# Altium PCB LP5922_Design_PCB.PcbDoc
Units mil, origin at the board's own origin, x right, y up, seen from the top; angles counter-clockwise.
Board outline 3530 x 2780 mil, 4 copper layers (Top Layer, Signal Layer 1, Signal Layer 2, Bottom Layer), stack 79.834 mil thick; 57 components, 18 nets, 103 pads, 46 vias.
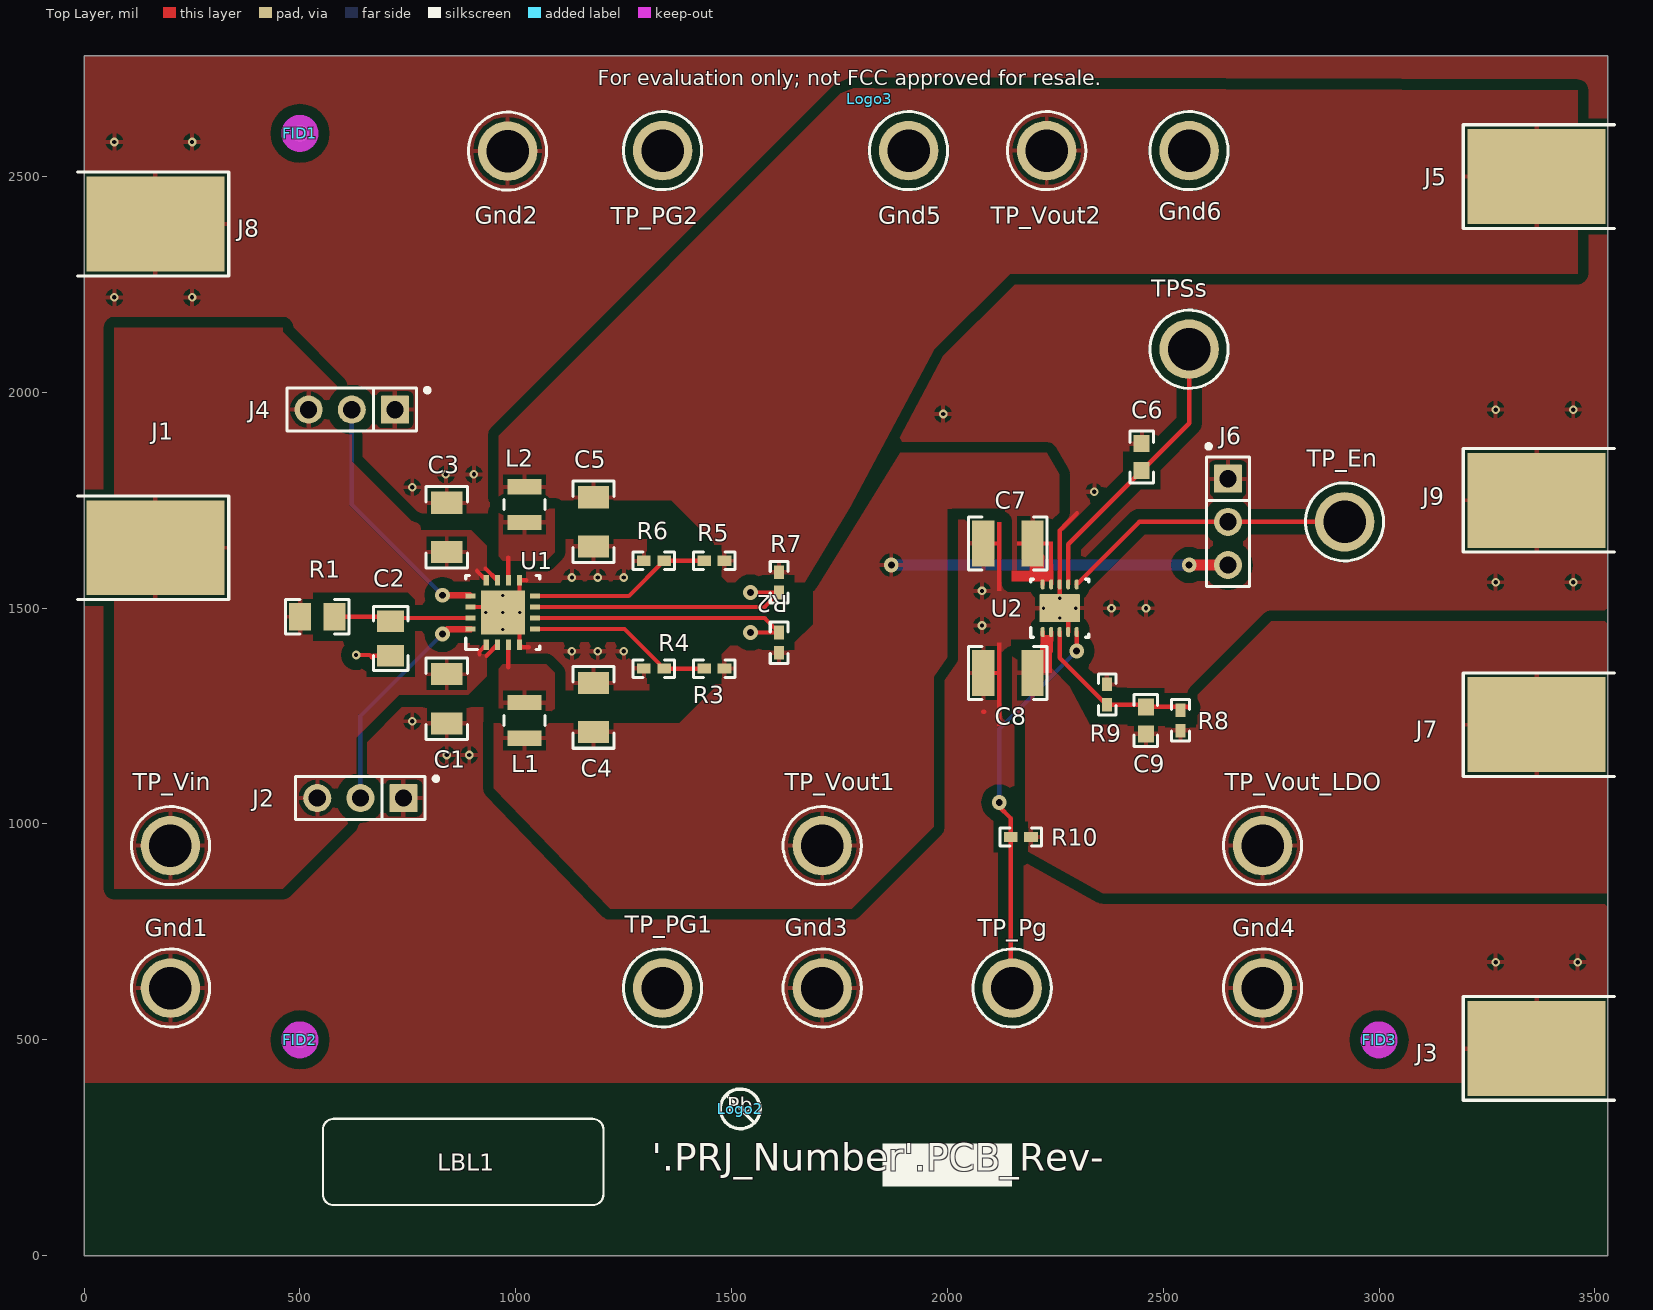
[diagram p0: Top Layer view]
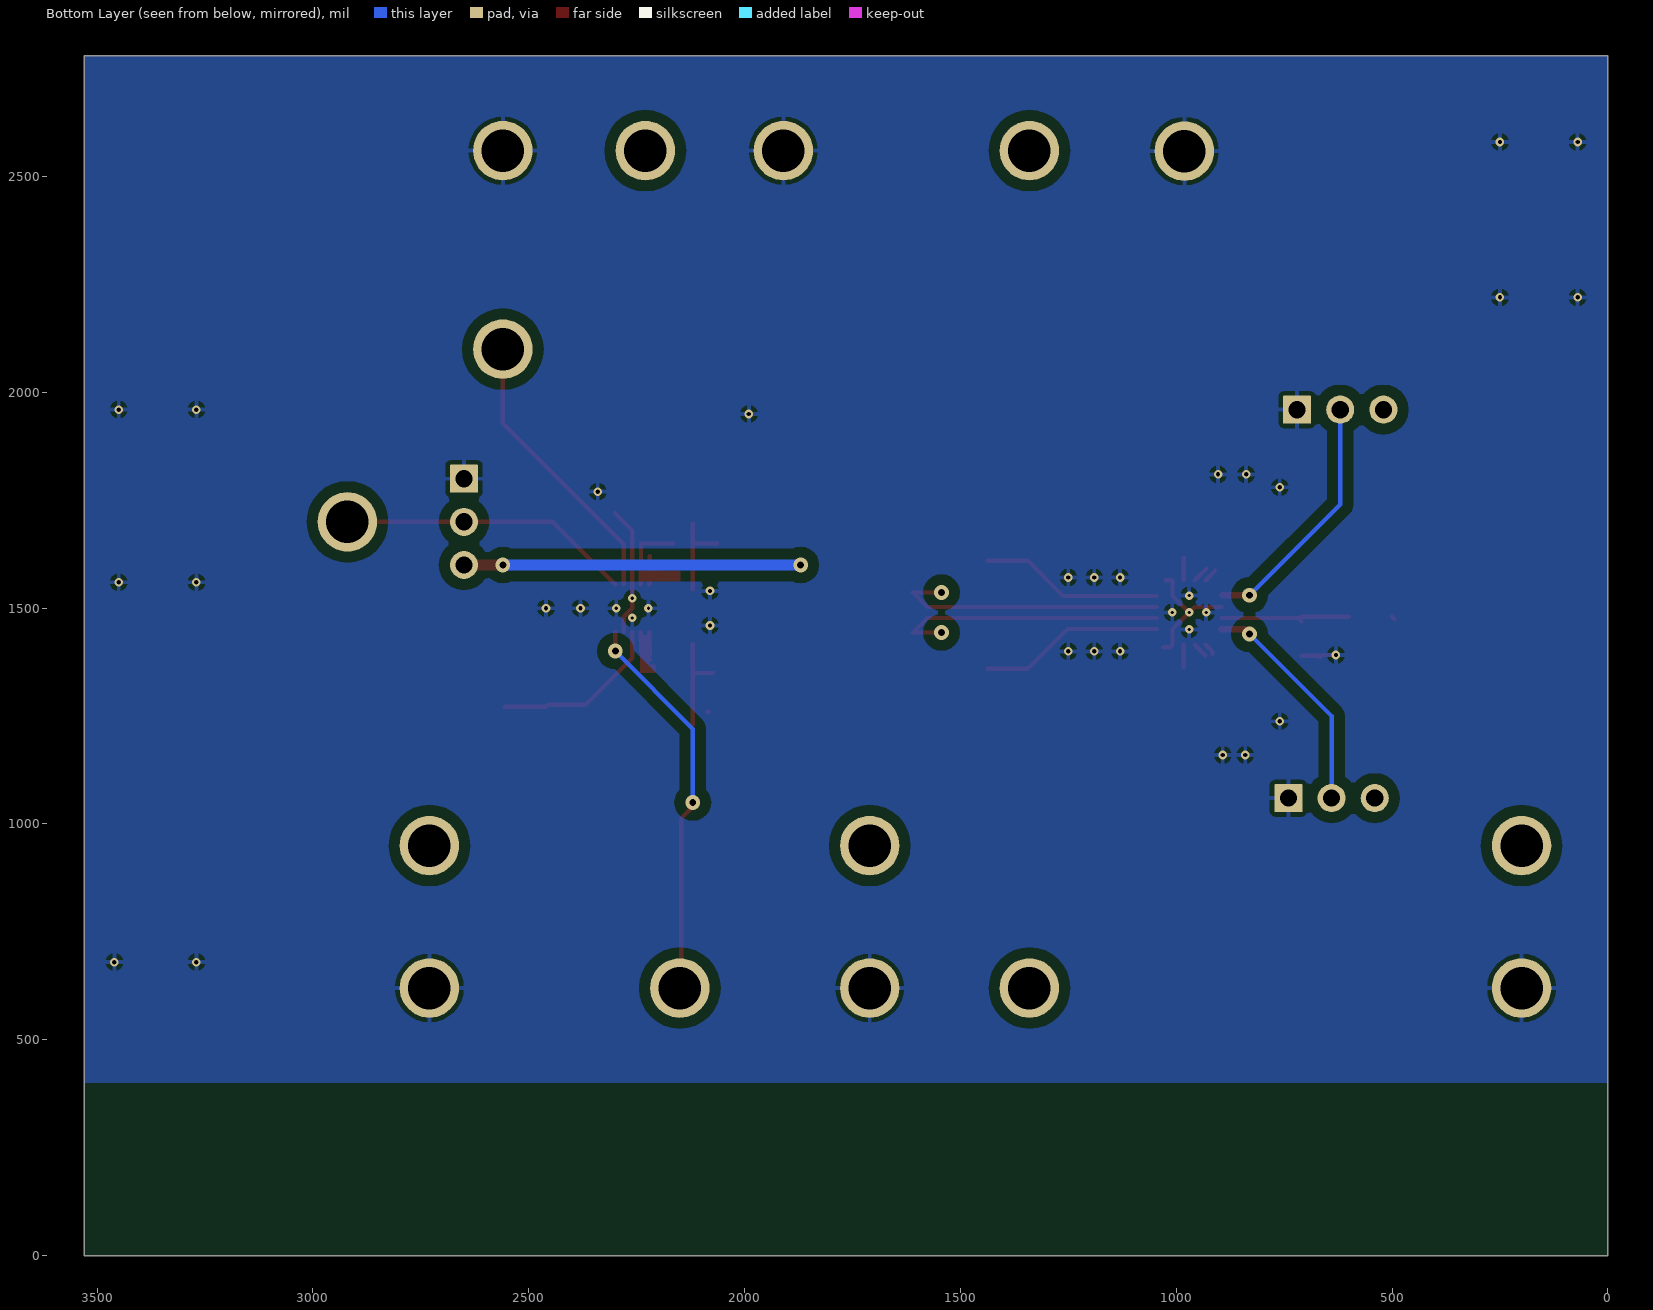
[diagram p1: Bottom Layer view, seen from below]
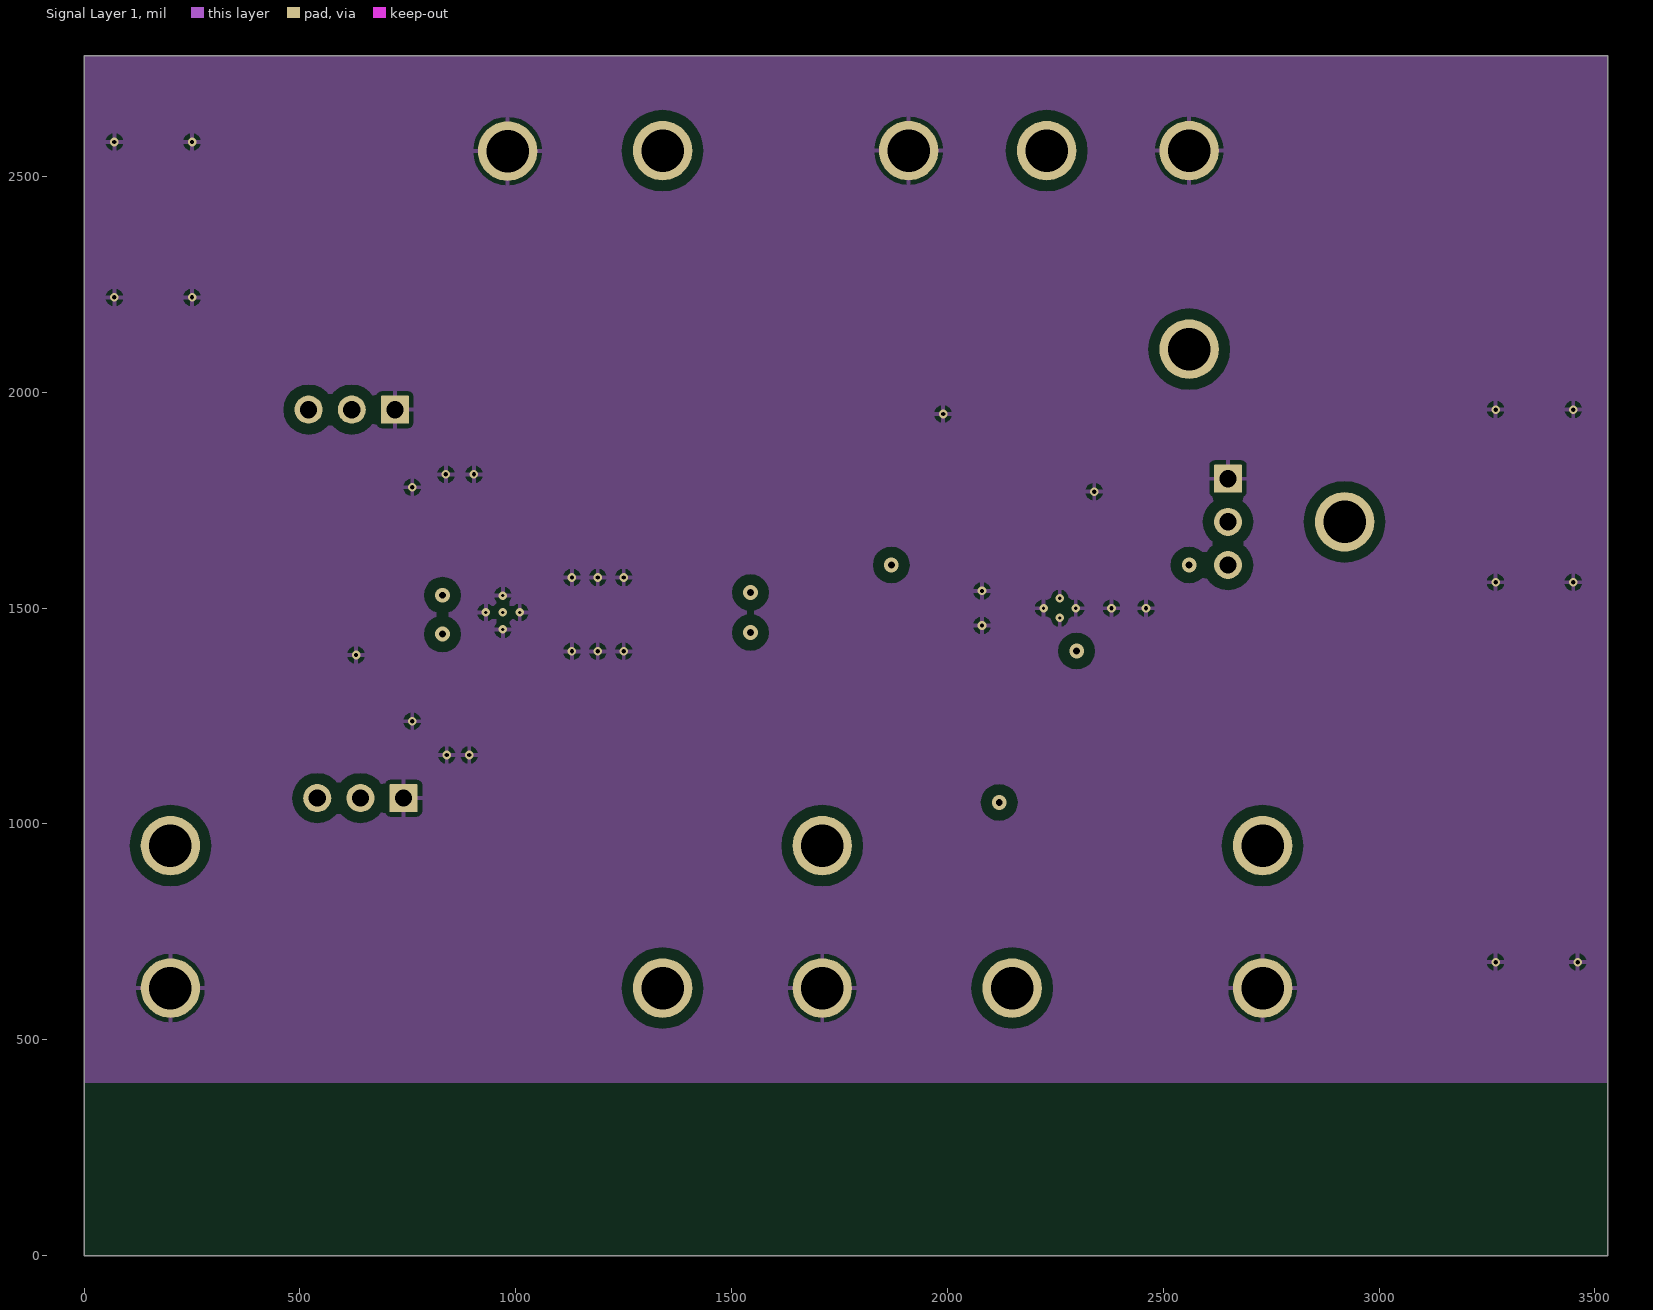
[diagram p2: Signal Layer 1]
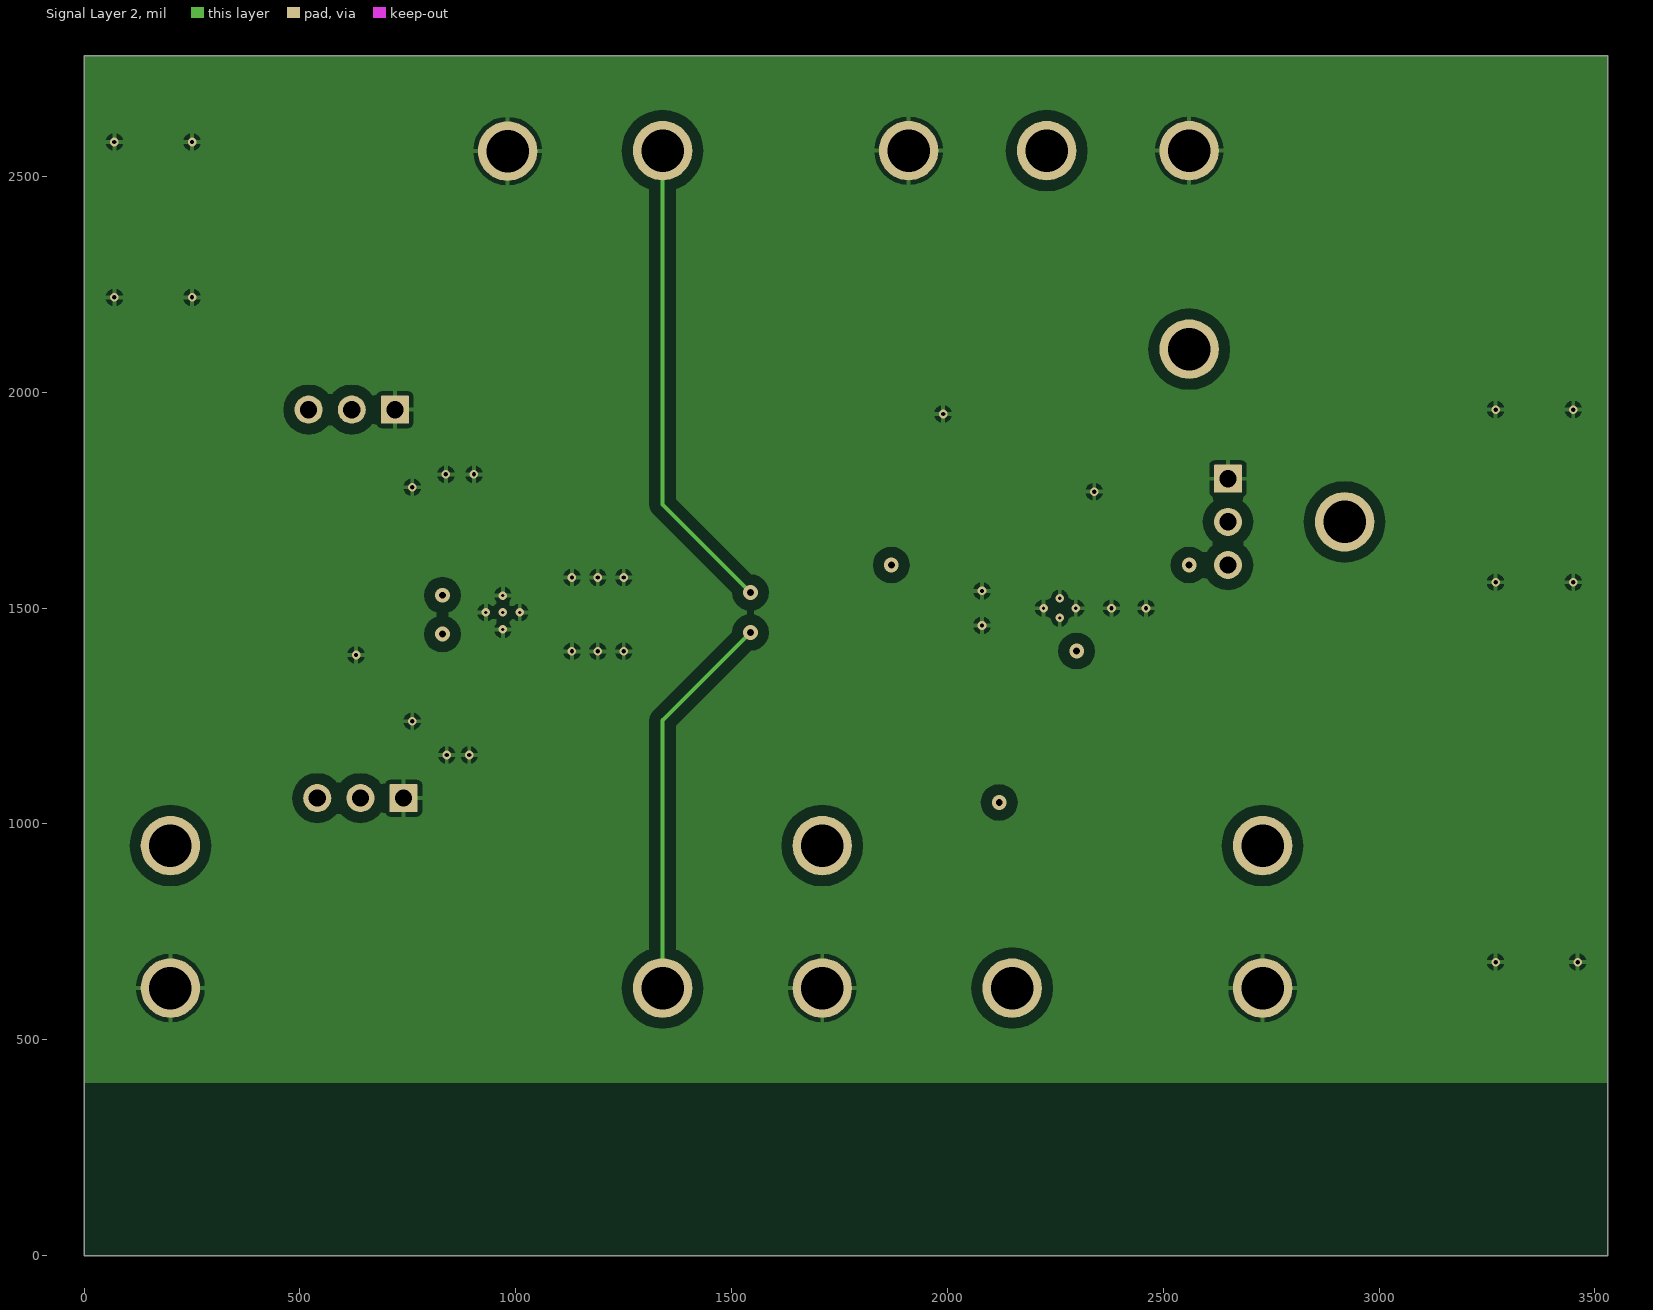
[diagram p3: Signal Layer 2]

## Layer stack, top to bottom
Top Solder: solder mask 0.4, Solder Resist, Dk 3.5
Top Layer: signal copper 1.4
Dielectric1: core 59.2, FR-4, Dk 4.8
Signal Layer 1: signal copper 1.417
Dielectric 3: prepreg 5, Dk 4.2
Signal Layer 2: signal copper 1.417
Dielectric 2: core 10, Dk 4.2
Bottom Layer: signal copper 1.4
Bottom Solder: solder mask 0.4, Solder Resist, Dk 3.5

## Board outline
0,0 3530,0 3530,2780 0,2780

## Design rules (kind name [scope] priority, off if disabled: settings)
AcuteAngle [All] p1: minimum=4.50000000000000E+0001 checktracksonly=FALSE
AssemblyTestPointUsage [All] p1: valid=2
Clearance Clearance_Keepouts [((IsTrack Or IsArc) And Not InPoly) And IsFree and IsKeepOut vs ((IsTrack Or IsArc) And Not InPoly) And IsFree and IsKeepOut] p1: gap=0
Clearance Clearance_Poly [InPolygon] p2: gap=25
Clearance [All] p3: gap=7.87
ComponentClearance ComponentClearance_MountingHoles_FiducialMarks [InComponentClass('Mounting Holes') vs InComponentClass('FiducialMark')] p1: gap=50 collisioncheckmode=3 verticalgap=10 showdistances=FALSE
ComponentClearance ComponentClearance_Shunt [InComponentClass('Header') vs InComponentClass('Shunt')] p2: gap=0 collisioncheckmode=3 verticalgap=0 showdistances=FALSE
ComponentClearance ComponentClearance_Logo [InComponentClass('Logo')] p3: gap=50 collisioncheckmode=3 verticalgap=10 showdistances=FALSE
ComponentClearance ComponentClearance_ScrewToNut [(HasFootprint('NY PMS 440 0025 PH')) vs (HasFootprint('Keystone_1902C'))] p4: gap=5 collisioncheckmode=3 verticalgap=10 showdistances=FALSE
ComponentClearance ComponentClearance_MountingHoles [InComponentClass('Mounting Holes')] p5: gap=250 collisioncheckmode=3 verticalgap=100000 showdistances=FALSE
ComponentClearance ComponentClearance_SmallPassives [HasFootprint('0201*') or HasFootprint('0402*') or HasFootprint('0508') or HasFootprint('0603*') or HasFootprint('0612') or HasFootprint('0805*') or HasFootprint('0815*') or HasFootprint('0830*') or HasFootprint('1206*') or HasFootprint('1210*') or HasFootprint('1808*') or HasFootprint('1812*') or HasFootprint('1825*') or HasFootprint('2010*') or HasFootprint('2220*') or HasFootprint('2225*') or HasFootprint('2512*') or HasFootprint('2728*') or HasFootprint('3518*') vs HasFootprint('0201*') or HasFootprint('0402*') or HasFootprint('0508') or HasFootprint('0603*') or HasFootprint('0612') or HasFootprint('0805*') or HasFootprint('0815*') or HasFootprint('0830*') or HasFootprint('1206*') or HasFootprint('1210*') or HasFootprint('1808*') or HasFootprint('1812*') or HasFootprint('1825*') or HasFootprint('2010*') or HasFootprint('2220*') or HasFootprint('2225*') or HasFootprint('2512*') or HasFootprint('2728*') or HasFootprint('3518*')] p6: gap=14.96 collisioncheckmode=3 verticalgap=10 showdistances=FALSE
ComponentClearance ComponentClearance_THtoSMT [IsThruComponent vs IsSMTComponent] p7: gap=40 collisioncheckmode=3 verticalgap=30 showdistances=FALSE
ComponentClearance ComponentClearance_THtoTH [IsThruComponent vs IsThruComponent] p8: gap=30 collisioncheckmode=3 verticalgap=30 showdistances=FALSE
ComponentClearance [All] p9: gap=30 collisioncheckmode=3 verticalgap=10 showdistances=FALSE
DiffPairsRouting [All] p1: maxlimit=100 minlimit=10 mostfreqgap=10 toplayer_minwidth=15 toplayer_maxwidth=15 toplayer_prefwidth=15 midlayer1_minwidth=15 midlayer1_maxwidth=15 midlayer1_prefwidth=15 midlayer2_minwidth=15 midlayer2_maxwidth=15 midlayer2_prefwidth=15 bottomlayer_minwidth=15 bottomlayer_maxwidth=15 bottomlayer_prefwidth=15 maxuncoupledlength=1000
FabricationTestPointUsage TestPointUsage [All] p1: valid=2 allowmultiple=FALSE
FabricationTestpoint Testpoint [All] p1: side=3 testpointundercomponent=TRUE minsize=40 maxsize=100 preferedsize=60 minholesize=0 maxholesize=40 preferedholesize=32 testpointgrid=1 allowsidetop=TRUE allowsidebottom=TRUE usegrid=TRUE gridtolerance=0.01
FanoutControl Fanout_LCC [IsLCC] p1: bgadir=Out bgaviamode=Centered fanoutstyle=Auto fanoutdirection=Alternating viagrid=1 // Fanout_LCC (Default Rule)
FanoutControl Fanout_BGA [IsBGA] p2: bgadir=Out bgaviamode=Centered fanoutstyle=Auto fanoutdirection=Alternating viagrid=1 // Fanout_BGA (Default Rule)
FanoutControl Fanout_Default [All] p4: bgadir=Out bgaviamode=Centered fanoutstyle=Auto fanoutdirection=Alternating viagrid=1 // Fanout_Default (Default Rule)
FanoutControl Fanout_Small [(CompPinCount < 5)] p5: bgadir=Out bgaviamode=Centered fanoutstyle=Auto fanoutdirection=OutThenIn viagrid=1 // Fanout_Small (Default Rule)
HoleSize [All] p1: absolutevalues=TRUE maxlimit=251 minlimit=7.87 maxpercent=80.000 minpercent=20.000
MinimumAnnularRing MinimumAnnularRing_ThermalPadVias [IsVia and InAnyComponent] p1: minimumring=5.91
MinimumAnnularRing [All] p2: minimumring=8
MinimumSolderMaskSliver MinimumSolderMaskSliver_Logo [InComponentClass('Logo') vs InComponentClass('Logo')] p1: minsoldermaskwidth=0.7
MinimumSolderMaskSliver [All] p2: minsoldermaskwidth=3.94
PlaneConnect [All] p1: planeconnectstyle=Relief reliefexpansion=10 reliefentries=4 reliefconductorwidth=10 reliefairgap=10
PolygonConnect [All] p1: connectstyle=Relief reliefconductorwidth=10 reliefentries=4 polygonreliefangle="90 Angle" airgapwidth=10
RoutingVias ThermalPadVias [IsVia and InAnyComponent] p1: holewidth=7.87 width=19.68 viastyle="Through Hole" minholewidth=7.87 minwidth=19.68 maxholewidth=12.99 maxwidth=23.62
RoutingVias [All] p2: holewidth=16 width=34 viastyle="Through Hole" minholewidth=7.87 minwidth=26 maxholewidth=40 maxwidth=65
SilkToBoardRegionClearance [Not ((IsComment or IsDesignator) And (Hide <> 'False')) and not InRegion(1000,500,4000,800)] p1:
SilkToSilkClearance SilkToSilkClearance_Pb-FreeLogo [(HasFootprint('Pb-Free_Overlay_Medium') OR HasFootprint('Pb-Free_Overlay_Small')) vs (HasFootprint('Pb-Free_Overlay_Medium') OR HasFootprint('Pb-Free_Overlay_Small'))] p1: silktosilkclearance=0
SilkToSilkClearance [All] p2: silktosilkclearance=4
SilkToSolderMaskClearance SilkToComponentPadClearance [IsPad and InAnycomponent] p1: minsilkscreentomaskgap=5 clearancetoexposedcopper=TRUE
SilkToSolderMaskClearance "Silk to Solder Mask Opening" [All] p2: minsilkscreentomaskgap=4 clearancetoexposedcopper=FALSE
SolderMaskExpansion [All] p1: expansion=1.97
Width [All] p1: maxlimit=100 minlimit=6 preferedwidth=10 checkconnectedcopper=TRUE
15 further rules are at their usual default settings.

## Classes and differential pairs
component class Label: LBL1
component class AssemblyNote: ZZ1 ZZ2 ZZ3 ZZ4
component class FiducialMark: FID1 FID2 FID3
component class LP5922_Design_EVM_Hardware: FID1 FID2 FID3 LBL1 Logo2 Logo3 ZZ1 ZZ2 ZZ3 ZZ4
component class Header: J2 J4 J6
component class LP5922_Design_BlankSheet: C1 C2 C3 C4 C5 C6 C7 C8 C9 Gnd1 Gnd2 Gnd3 Gnd4 Gnd5 Gnd6 J1 J2 J3 J4 J5 J6 J7 J8 J9 L1 L2 R1 R2 R3 R4 R5 R6 R7 R8 R9 R10 TP_En TP_Pg TP_PG1 TP_PG2 TP_Vin TP_Vout1 TP_Vout2 TP_Vout_LDO TPSs TPVout2 U1 U2

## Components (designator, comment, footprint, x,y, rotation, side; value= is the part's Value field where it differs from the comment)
C1 "C3216X5R0J226M" 1206 840,1290 r270 top
C2 "0805YC474JAT2A" 0805_HV 710,1430 r270 top
C3 "C3216X5R0J226M" 1206 840,1687.09 r90 top
C4 "C3216X5R0J476M" 1206 1180,1270 r90 top
C5 "C3216X5R0J476M" 1206 1180,1700 r270 top
C6 "GRM188R71A124KA01D" 0603 2450,1850 r90 top
C7 "C1210C226K9RACTU" 1210 2140,1650 r180 top
C8 "C1210C226K9RACTU" 1210 2140,1350 r180 top
C9 "GRM188R71H103KA01D" 0603 2460,1240 r90 top
FID1 "Fiducial" Fiducial10-20 500,2600 r0 top
FID2 "Fiducial" Fiducial10-20 500,500 r0 top
FID3 "Fiducial" Fiducial10-20 3000,500 r0 top
Gnd1 "Suggest using a net name here" Keystone1502-2 200,620 r0 top
Gnd2 "Suggest using a net name here" Keystone1502-2 981,2559 r0 top
Gnd3 "Suggest using a net name here" Keystone1502-2 1710,620 r0 top
Gnd4 "Suggest using a net name here" Keystone1502-2 2730,620 r0 top
Gnd5 "Suggest using a net name here" Keystone1502-2 1910,2560 r0 top
Gnd6 "Suggest using a net name here" Keystone1502-2 2560,2560 r0 top
J1 "6091" 6091 -20,1640 r0 top
J2 "HTSW-103-07-G-S" Samtec_HTSW-103-07-G-S 640,1060 r180 top
J3 "6092" 6092 3550,480 r180 top
J4 "HTSW-103-07-G-S" Samtec_HTSW-103-07-G-S 620,1960 r180 top
J5 "6091" 6091 3550,2500 r180 top
J6 "HTSW-103-07-G-S" Samtec_HTSW-103-07-G-S 2650,1700 r270 top
J7 "6091" 6091 3550,1230 r180 top
J8 "6092" 6092 -20,2390 r0 top
J9 "6092" 6092 3550,1750 r180 top
L1 "DFE252012PD-1R0M" DFE252012P 1020,1240 r270 top
L2 "DFE252012PD-1R0M" DFE252012P 1020,1740 r90 top
LBL1 "Size: 0.65\" x 0.20 \"" Label_650x200 878,217 r0 top
Logo2 "Pb-Free Symbol" Pb-Free_Overlay_Small 1520,340 r0 top
Logo3 "FCC disclaimer" FCC_disclaimer 1820,2680 r0 top
R1 "CRCW08054R99FKEA" 0805_HV 540,1480 r0 top
R2 "CRCW040210K0DHEDP" 0402 1610,1420 r270 top
R3 "CRCW0402619RFKED" 0402 1460,1360 r0 top
R4 "CRCW040210K0DHEDP" 0402 1320,1360 r0 top
R5 "CRCW040216K2FKED" 0402 1460,1610 r0 top
R6 "CRCW040210K0DHEDP" 0402 1320,1610 r0 top
R7 "CRCW040210K0DHEDP" 0402 1610,1560 r90 top
R8 "CRCW040232K4FKED" 0402 2540,1240 r270 top
R9 "CRCW040212K4FKED" 0402 2370,1300 r270 top
R10 "CRCW040210K0DHEDP" 0402 2170,970 r0 top
TP_En "Suggest using a net name here" Keystone1502-2 2920,1700 r0 top
TP_Pg "Suggest using a net name here" Keystone1502-2 2150,620 r0 top
TP_PG1 "Suggest using a net name here" Keystone1502-2 1340,620 r0 top
TP_PG2 "Suggest using a net name here" Keystone1502-2 1340,2560 r0 top
TP_Vin "Suggest using a net name here" Keystone1502-2 200,950 r90 top
TP_Vout1 "Suggest using a net name here" Keystone1502-2 1710,950 r0 top
TP_Vout2 "Suggest using a net name here" Keystone1502-2 2230,2560 r90 top
TP_Vout_LDO "Suggest using a net name here" Keystone1502-2 2730,950 r90 top
TPSs "Suggest using a net name here" Keystone1502-2 2560,2100 r0 top
U1 "LM26420XSQX/NOPB" RUM0016A 970,1490 r90 top
U2 "LP592201DSCR" DSC0010J 2260,1500 r90 top
ZZ1 "This Assembly Note is for PCB labels only" AssemblyNoteLabel 185,3938 r0 top
ZZ2 "These assemblies are ESD sensitive, ESD precautions shall be observed." AssemblyNote 185,3829.11 r0 top
ZZ3 "These assemblies must be clean and free from flux and all contaminants. Use of no clean flux is not acceptable." AssemblyNote 185,3740.56 r0 top
ZZ4 "These assemblies must comply with workmanship standards IPC-A-610 Class 2, unless otherwise specified." AssemblyNote 185,3652 r0 top

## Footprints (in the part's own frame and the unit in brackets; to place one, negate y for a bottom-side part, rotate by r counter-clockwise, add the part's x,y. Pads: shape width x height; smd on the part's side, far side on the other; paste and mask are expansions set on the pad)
0402 [mm] "0402 from SM-752 data"
  rect 0.8x0.6 smd: 1(-0.6,0) 2(0.6,0)
  silkscreen extent -1.22,-0.52 1.22,0.52, body extent -0.55,-0.3 0.55,0.3, height 0.6
0603 [mm] "0603 from SM-752 data"
  rect 1x0.95 smd: 1(-0.8,0) 2(0.8,0)
  silkscreen extent -1.52,-0.69 1.52,0.69, body extent -0.87,-0.47 0.87,0.47, height 1
0805_HV [mil] "0805 with 30mil clearance between pads"
  rect 50x63 smd: 1(-40,0) 2(40,0)
  silkscreen extent -74,-40 74,40, body extent -43,-29 43,29, height 57
1206 [mm] "1206 from SM-752 data"
  rect 1.3x1.85 smd: 1(-1.45,0) 2(1.45,0)
  silkscreen extent -2.4,-1.21 2.4,1.21, body extent -1.7,-0.9 1.7,0.9, height 1.35
1210 [mm] "1210 from SM-752 data"
  rect 1.3x2.7 smd: 1(-1.45,0) 2(1.45,0)
  silkscreen extent -2.32,-1.57 2.32,1.57, body extent -1.7,-1.35 1.7,1.35, height 1.35
6091 [mil] "Keystone Insulated End Launch Banana Jack"
  rect 320x220 smd: 1(185,0)
  silkscreen extent 5,-120 355,120, body extent -666,-216 271,216, height 227
6092 [mil] "Keystone Insulated End Launch Banana Jack"
  rect 320x220 smd: 1(185,0)
  silkscreen extent 5,-120 355,120, body extent -666,-216 271,216, height 227
AssemblyNote [mil] "Assembly Note"
AssemblyNoteLabel [mil] "Assembly Note for PCB Labels"
DFE252012P [mm] "TOKO, Pad sizes increased as per request"
  rect 0.9x2 smd: 1(-1.05,0) 2(1.05,0)
  silkscreen extent -0.3,-1.2 0.3,1.2, body extent -1.35,-1.1 1.35,1.1, height 1.2
DSC0010J [mm] "SON, 10-Leads, Body 3x3mm, Pitch 0.5mm, Thermal Pad 2.4x1.65mm, TI Recommended"
  rrect100% 0.6x0.24 smd: 1(-1.4,1) 2(-1.4,0.5) 3(-1.4,0) 4(-1.4,-0.5) 5(-1.4,-1) 6(1.4,-1) 7(1.4,-0.5) 8(1.4,0) 9(1.4,0.5) 10(1.4,1)
  rrect6% 1.65x2.4 smd paste-0.825: 11(0,0)
  silkscreen extent -1.7,-1.7 1.7,1.7, body extent -1.57,-1.57 1.57,1.57, height 0.81
FCC_disclaimer [mil]
Fiducial10-20 [mm]
  round 1 smd mask+0.5: 1(0,0)
  Top Layer keep-out circle w1.178: c0,0 r0.5
Keystone1502-2 [mm] "Double Turret"
  round 3.5 hole 2.5: 1(0,0)
  silkscreen extent -2.3,-2.3 2.3,2.3, body extent -1.6,-1.6 1.59,1.6, height 5.62
Label_650x200 [mil] "Thermal Transfer Label"
  silkscreen extent -325,-100 325,100, body extent -325,-100 325,100, height 1
Pb-Free_Overlay_Small [mil]
  silkscreen extent -46,-46 46,46
RUM0016A [mm] "QFN, 16-Leads, Body 4.1x4.1mm, Pitch 0.65mm, Thermal Pad 2.6x2.6mm"
  rect 0.6x0.3 smd: 1(-1.9,0.975) 2(-1.9,0.325) 3(-1.9,-0.325) 4(-1.9,-0.975) 9(1.9,-0.975) 10(1.9,-0.325) 11(1.9,0.325) 12(1.9,0.975)
  rect 0.3x0.6 smd: 5(-0.975,-1.9) 6(-0.325,-1.9) 7(0.325,-1.9) 8(0.975,-1.9) 13(0.975,1.9) 14(0.325,1.9) 15(-0.325,1.9) 16(-0.975,1.9)
  rect 2.6x2.6 smd paste-1.3: 17(0,0)
  silkscreen extent -2.17,-2.17 2.17,2.17, body extent -2.07,-2.07 2.07,2.07, height 0.8
Samtec_HTSW-103-07-G-S [mm] "Samtec 100mil, 1x3, 230 mil above insulator"
  rrect6% 1.65x1.65 hole 1.016: 1(-2.54,0)
  round 1.65 hole 1.016: 2(0,0) 3(2.54,0)
  silkscreen extent -4.57,-1.27 3.81,1.27, body extent -3.81,-1.27 3.81,1.27, height 8.38

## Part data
C1 C3: "CAP, CERM, 22 µF, 6.3 V, +/- 20%, X5R, 1206"
C2: "CAP, CERM, 0.47 µF, 16 V, +/- 5%, X7R, 0805"
C4 C5: "CAP, CERM, 47 µF, 6.3 V, +/- 20%, X5R, 1206"
C6: "CAP, CERM, 0.12 µF, 10 V, +/- 10%, X7R, 0603"
C7 C8: "CAP, CERM, 22 µF, 6.3 V, +/- 10%, X7R, 1210"
C9: "CAP, CERM, 0.01 µF, 50 V, +/- 10%, X7R, 0603"
FID1 FID2 FID3: "Fiducial mark.  There is nothing to buy or mount."
Gnd1 Gnd2 Gnd3 Gnd4 Gnd5 Gnd6 TP_En TP_Pg TP_PG1 TP_PG2 TP_Vin TP_Vout1 TP_Vout2 TP_Vout_LDO TPSs: library part 1502-2, "Terminal, Turret, TH, Double"
J1 J5 J7: "Standard Banana Jack, Insulated, Red"
J2 J4 J6: "Header, 100mil, 3x1, Gold, TH"
J3 J8 J9: "Standard Banana Jack, Insulated, Black"
L1 L2: "Inductor, Shielded, 1 µH, 3.8 A, 0.035 ohm, AEC-Q200 Grade 1, SMD"
LBL1: library part THT-14-423-10, "Thermal Transfer Printable Labels, 0.650\" W x 0.200\" H - 10,000 per roll"
Logo2: library part Pb-Free
Logo3: library part FCC_disclaimer, "FCC_disclaimer"
R1: "RES, 4.99, 1%, 0.125 W, 0805"
R2 R4 R6 R7 R10: "RES, 10.0 k, 0.5%, 0.063 W, 0402"
R3: "RES, 619, 1%, 0.063 W, 0402"
R5: "RES, 16.2 k, 1%, 0.063 W, 0402"
R8: "RES, 32.4 k, 1%, 0.063 W, 0402"
R9: "RES, 12.4 k, 1%, 0.063 W, 0402"
U1: "Dual 2-A, High Frequency Synchronous Buck Regulator, RUM0016A (WQFN-16)"
U2: "LP592201, DSC0010J"
ZZ1: library part AssemblyNoteLabel
ZZ2 ZZ3 ZZ4: library part AssemblyNote

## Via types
v1: diameter 20, hole 10, Top Layer to Bottom Layer, 29 vias
v2: diameter 19.68, hole 7.87, Top Layer to Bottom Layer, 9 vias
v3: diameter 34, hole 16, Top Layer to Bottom Layer, 8 vias

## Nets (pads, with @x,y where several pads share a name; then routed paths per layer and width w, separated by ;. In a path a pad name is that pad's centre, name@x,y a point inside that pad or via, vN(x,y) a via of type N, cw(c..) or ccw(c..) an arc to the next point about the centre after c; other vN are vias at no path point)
GND: C1.2 C2.2 C3.2 C4.2 C5.2 C6.2 C7.2 C8.2 Gnd1.1 Gnd2.1 Gnd3.1 Gnd4.1 Gnd5.1 Gnd6.1 J2.1 J3.1 J4.1 J6.1 J8.1 J9.1 R4.1 R6.1 R9.1 U1.4 U1.9 U1.14 U1.17 U2.4 U2.8 U2.11 | length 686.6
  Top Layer w10: v1(630,1391.57) 661.57,1391.57 666.57,1386.57 670,1390 C2.2 ; U1.14 957.2,1502.8 v2(970,1490) ; 1024.09,1564.8 U1.9 1008.39,1528.39 v2(970,1490) ; 1030,1409.29 1014.29,1409.29 U1.4 1008.39,1451.61 v2(970,1490) ; 2083.07,1260 2085.04,1260 ; U2.4 2279.68,1480.32 U2.11 v2(2260,1522.64) U2.8 2260,1680 2300,1720
  other v1: 3270,680 3460,680 840,1160 892,1160 760,1238 1130,1400 1190,1400 1250,1400 2080,1460 2380,1500 2460,1500 2080,1540 3270,1560 3450,1560 1130,1571 1190,1571 1250,1571 2340,1770 760,1780 838,1810 903,1810 1990,1950 3270,1960 3450,1960 70,2220 250,2220 70,2580 250,2580
  other v2: 970,1450.63 2260,1477.36 930.63,1490 1009.37,1490 2222.6,1500 2297.4,1500 970,1529.37
NetC1_1: C1.1 C3.1 J1.1 J2.3 J4.3 R1.1 TP_Vin.1 U1.1 U1.2 U1.11 U1.12 | length 140.1
  Top Layer w10: R1.1@495,1475 R1.1 ; 910,1586.42 U1.12 ; 915.71,1393.39 915.71,1399.29 U1.1 ; 930,1592.01 U1.11 ; 932.01,1390 U1.2
NetC2_1: C2.1 R1.2 U1.15 | length 298.2
  Top Layer w10: R1.2@600,1480 C2.1@710,1480 ; C2.1 717.2,1477.2 U1.15
NetC4_1: C4.1 C7.1 J6.3 L1.2 R2.2 R3.2 TP_Vout1.1 U2.9 U2.10 | length 939.8
  Top Layer w10: C7.1@2220,1620 U2.10 ; 2240,1650 U2.9
  Top Layer w25: v3(2560,1600) J6.3
  Bottom Layer w25: v3(1870,1600) v3(2560,1600)
NetC5_1: C5.1 J5.1 L2.2 R5.2 R7.2 TP_Vout2.1
NetC6_1: C6.1 TPSs.1 U2.7 | length 661
  Top Layer w10: U2.7 2279.68,1648.19 C6.1 2560,1928.5 TPSs.1
NetC8_1: C8.1 C9.1 J7.1 R8.2 R10.2 TP_Vout_LDO.1 U2.1 U2.2 | length 128.5
  Top Layer w10: C8.1@2219.74,1380 2240.06,1400.31 ; C8.1@2220,1390 U2.1 ; 2240,1400 U2.2
NetC9_2: C9.2 R8.1 R9.2 U2.3 | length 404
  Top Layer w10: U2.3 2260,1384.88 2368.5,1276.38 R9.2 2455.12,1276.38 C9.2 2554.88,1271.5 2556.38,1270
NetJ2_2: J2.2 U1.16 | length 538.7
  Top Layer w10: v3(830,1440) v3@841.61,1451.61
  Top Layer w15: v3@841.61,1451.61 U1.16
  Bottom Layer w10: J2.2 640,1250 v3(830,1440) v3@830,1450
NetJ4_2: J4.2 U1.13 | length 582.9
  Top Layer w10: U1.13@893.58,1530 U1.13
  Top Layer w15: v3(830,1530) U1.13@893.58,1530
  Bottom Layer w10: J4.2 620,1740 v3(830,1530)
NetJ6_2: J6.2 TP_En.1 U2.6 | length 680.6
  Top Layer w10: U2.6 2444.25,1700 J6.2 TP_En.1
NetL1_1: L1.1 U1.3 | length 52.4
  Top Layer w10: 982.8,1362.8 U1.3
NetL2_1: L2.1 U1.10 | length 52.4
  Top Layer w10: U1.10 982.8,1617.2
NetR2_1: R2.1 TP_PG1.1 U1.6 | length 1553.5
  Top Layer w10: U1.6 1576.42,1477.2 R2.1 v3(1543.62,1443.62)
  Signal Layer 2 w10: TP_PG1.1 1340,1240 v3(1543.62,1443.62)
NetR3_1: R3.1 R4.2 U1.5 | length 429.5
  Top Layer w10: U1.5 1252.01,1451.61 R4.2 R3.1
NetR5_1: R5.1 R6.2 U1.8 | length 425.4
  Top Layer w10: U1.8 1262.01,1528.39 R6.2 R5.1
NetR7_1: R7.1 TP_PG2.1 U1.7 | length 1753.5
  Top Layer w10: U1.7 1576.42,1502.8 R7.1 v3(1543.62,1536.38)
  Signal Layer 2 w10: TP_PG2.1 1340,1740 v3(1543.62,1536.38)
NetR10_1: R10.1 TP_Pg.1 U2.5 | length 911.2
  Top Layer w10: v3(2120,1050) 2120,1040 2146.38,1013.62 R10.1 2146.38,623.62 TP_Pg.1 ; v3(2299.37,1400.63) U2.5
  Bottom Layer w10: v3(2120,1050) 2120,1220 v3(2299.37,1400.63)
pads on no net: FID1.1 FID2.1 FID3.1

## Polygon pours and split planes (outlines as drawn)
GND on Top Layer "TOP_LAYER_GND_P064" (solid, remove dead copper, pour order 64): 0,2780 3530,2780 3530,400 0,400 0,2780
NetC4_1 on Top Layer "TOP_LAYER_NETC4_1_P062" (solid, remove dead copper, pour order 62): 948.75,1233.14 948.75,1083.14 1218.75,803.14 1778.75,803.14 1968.75,993.14 1968.75,1341.29 2000.11,1386.07 2000.11,1416.07 2000.11,1435.45 2000.11,1456.07 1999.89,1480 1999.89,1503.93 1999.89,1523.93 1999.89,1563.93 1999.89,1579.91 1999.89,1590 1999.89,1618.71 1999.9,1640 2000.01,1679.13 2000.01,1690 2000.01,1720 2000.01,1729.99 2010,1729.99 2020.42,1729.99 2100,1729.99 2101.92,1729.91 2120.23,1729.99 2140.28,1709.95 2149.12,1701.1 2148.87,1569.88 2154.6,1564.1 2258.75,1564.1 2258.75,1573.14 2258.75,1593.14 2258.75,1633.14 2258.75,1733.14 2258.75,1810.74 2230,1860 1970,1860 1890.41,1860 1701.66,1554.72 1691.42,1539.75 1688.75,1539.75 1688.75,1463.14 1638.75,1413.14 1497.1,1413.14 1458.75,1374.79 1461.94,1371.6 1461.94,1316.33 1419.58,1273.97 1378.75,1233.14
NetC5_1 on Top Layer "TOP_LAYER_NETC5_1_P060" (solid, remove dead copper, pour order 60): 960,1900 960,1750 1360,1750 1460,1650 1460,1590 1490,1560 1670,1560 1775.01,1735.19 1970,2100 2145,2275 3460,2275 3460,2490 3460,2700 1830,2705 1782,2705 1753,2693
NetC8_1 on Top Layer "TOP_LAYER_NETC8_1_P050" (solid, remove dead copper, pour order 50): 2240,1400 2300,1400 2190,1400 2160,1400 2150,1400 2150,1285.52 2150,1257.64 2180,1252.48 2180,1120 2180,940 2360,840 3513.6,840 3530,840 3530,848.87 3530,900 3530,960 3530,1010 3530,1195.36 3530,1469.62 3454.64,1469.62 3027.97,1469.62 2930,1469.62 2749.62,1469.62 2580,1300 2580,1230 2330,1230
NetC1_1 on Top Layer "TOP_LAYER_NETC1_1_P026" (solid, remove dead copper, pour order 26): 70,1680 70,2150 460,2150 460,2140 610,1990 620,1980 620,1860 620,1840 757.93,1702.07 783,1692.63 800,1690 860.75,1690 932.38,1690 932.38,1382.38 932.38,1300 850,1300 730,1300 630,1200 630,1040 630,1020 460,850 70,850
NetL1_1 on Top Layer "TOP_LAYER_NETL1_1_P028" (solid, remove dead copper, pour order 28): 960,1370 960,1268.57 1020,1268.57 1090,1260 1090,1370 1040,1370 990,1370
NetL2_1 on Top Layer "TOP_LAYER_NETL2_1_P032" (solid, remove dead copper, pour order 32): 1090,1730 1090,1610 1010,1610 980,1610 960,1610 960,1730 980,1730 990,1730 1010,1730
GND on Signal Layer 1 "SIGNAL_LAYER_1_GND_P068" (solid, remove dead copper, pour order 68): 0,2780 3530,2780 3530,400 0,400 0,2780
GND on Signal Layer 2 "SIGNAL_LAYER_2_GND_P070" (solid, remove dead copper, pour order 70): 0,2780 3530,2780 3530,400 0,400 0,2780
GND on Bottom Layer "BOTTOM_LAYER_GND_P072" (solid, remove dead copper, pour order 72): 0,2780 3530,2780 3530,400 0,400 0,2780

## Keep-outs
Keep-Out Layer:
  text ".Layer_Name" at 577,-858.49 h60

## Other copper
Top Layer:
  rectangle net NetC4_1: 2161.5,1645 2245,1655
  rectangle net GND: 2059.69,1645 2120,1655
  rectangle net GND: 2115,1540 2125,1700
  rectangle net GND: 2070,1345 2120.31,1355
  rectangle net GND: 2115,1226.85 2125,1420
  rectangle net NetC8_1: 2206.91,1350 2242.68,1370
  rectangle net NetC8_1: 2220,1359.41 2242.68,1437.99
  rectangle net NetC4_1: 2190,1580 2220.39,1600
  rectangle net NetC4_1: 2148.87,1562.01 2240,1586.85
  pour cut-out: 750,1536.5 766.5,1520 766.5,1507.46 622.54,1507.46 593.5,1536.5
  pour cut-out: 960,1620 970,1610 960,1610
  pour cut-out: 1070,1610 1090,1630 1090,1610
  pour cut-out: 894.59,1682.7 940,1637.3 940,1682.7
  pour cut-out: 960,1370 970,1370 960,1360
  pour cut-out: 1070,1370 1090,1350 1090,1370
  pour cut-out: 780,1680 830,1680 886.26,1680 910,1680 930,1680 940,1670 940,1710 940,1720 780,1720 779.44,1680.56
  pour cut-out: 1110,1720 1380,1720 1380,1660 1110,1660
  pour cut-out: 1110,1310 1310,1310 1310,1280 1110,1280
  pour cut-out: 924.51,1230.95 924.51,1273.54 937.81,1260.24 937.81,1244.25
  pour cut-out: 730,1270 939.69,1270 934.51,1275.18 932.38,1277.31 932.38,1300 740,1300
  pour cut-out: 932.38,1342.09 890.29,1300 932.38,1300
  pour cut-out: 1309.69,1309.69 1309.69,1280 1410,1290 1440,1320 1440,1330 1309.69,1330
  pour cut-out: 1310,1530 1480,1530 1480,1550 1474.83,1550 1444.83,1580 1400,1580 1400,1642.44 1402.44,1640 1420,1640 1420,1670 1390,1700 1310,1700 1302.87,1692.87 1302.87,1642.91 1377.09,1642.91 1380,1640 1380,1580 1340,1580 1310,1550
  text ".Layer_Name" at 577,-858.49 h60
Bottom Layer:
  text ".Layer_Name" at 577,-858.49 h60

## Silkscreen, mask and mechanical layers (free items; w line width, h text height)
Top Overlay:
  region: 2150,260 1850,260 1850,160 2150,160
  text "'.PRJ_Number'.PCB_Rev-" at 1315,175.77 h108.27
  text ".Layer_Name" at 577,-858.49 h60
Bottom Overlay:
  text ".Layer_Name" at 577,-858.49 h60
Top Paste:
  text ".Layer_Name" at 577,-858.49 h60
Bottom Paste:
  text ".Layer_Name" at 577,-858.49 h60
Top Solder:
  text ".Layer_Name" at 577,-858.49 h60
  text ".Layer_Name" at 577,-858.49 h60
Bottom Solder:
  text ".Layer_Name" at 577,-858.49 h60
Drill Guide:
  text ".Layer_Name" at 577,-858.49 h60
M1 Board Outline:
  the board outline again, w10
  text ".Layer_Name" at 577,-858.49 h60
M2 Board Dimensions:
  rectangle: 125,-400 500,-275
  rectangle: 0,-275 125,-150
  lines w7: 0,-275 1000,-275 ; 125,-400 125,-150 ; 250,-400 250,-150 ; 500,-400 500,-150 ; 750,-400 750,-150 ; 0,-400 0,-150 1000,-150 1000,-400 0,-400
  text ".Layer_Name" at 577,-858.49 h60
M3 3D STEP Top:
  text ".Layer_Name" at 577,-858.49 h60
M4 3D STEP Bottom:
  text ".Layer_Name" at 577,-858.49 h60
M5 Assembly Top:
  lines w10: -292,-930.17 6308,-930.17 ; -292,-726.83 6310,-726.83 ; -292,-523.5 -292,-1133.5 3713,-1133.5 6310,-1133.5 6310,-523.5 -291.5,-523.5 -291.5,-1133.5 1284,-1133.5 ; 2173,-1133.5 2173,-523.5 ; 3440,-726.83 3440,-523.5 ; 4280,-726.83 4280,-523.5 ; 4902,-1140 4902,-937.17
  text "COMPONENTS MARKED 'DNP' SHOULD NOT BE POPULATED." at 1153.5,-318.5 h60
  text "ASSEMBLY VARIANT:" at 1153,-434 h60
  text ".VariantName" at 2189,-434 h60
  text "PCB VIEWED FROM TOP SIDE" at -228.5,-655.67 h60
  text "BOARD #:" at 2248,-655.67 h60
  text ".PRJ_Number" at 2793.5,-655.67 h60
  text "REV:" at 3638,-655.67 h60
  text ".PCB_Rev" at 3929.5,-655.67 h60
  text "SVN REV:" at 4476,-655.67 h60
  text ".VersionControl_RevNumber" at 4982,-655.67 h60
  text "TID #:" at 2248,-859 h60
  text ".TID" at 2793.5,-859 h60
  text "PLOT NAME =" at -228.5,-1064.34 h60
  text ".plot_File_Name" at 577,-1064.34 h60
  text "GENERATED    :" at 2250,-1064.34 h60
  text ".Print_Date" at 3119.5,-1064.34 h60
  text ".Print_Time" at 3848.5,-1064.34 h60
  text "TEXAS INSTRUMENTS" at 5113,-1064.34 h60
M6 Assembly Bottom:
  lines w10: -292.5,-727.33 6309.5,-727.33 ; -290.5,-930.67 6309.5,-930.67 ; 1115.5,-1140.5 1115.5,-937.67 ; 1737.5,-727.33 1737.5,-524 ; 2577.5,-727.33 2577.5,-524 ; 3844.5,-1134 3844.5,-524 ; 4733.5,-1134 6309,-1134 6309,-524 -292.5,-524 -292.5,-1134 2304.5,-1134 6309.5,-1134 6309.5,-524
  text "COMPONENTS MARKED 'DNP' SHOULD NOT BE POPULATED." at 6102,-318 h60
  text ".VariantName" at 5058,-434 h60
  text "ASSEMBLY VARIANT:" at 6097,-434 h60
  text ".VersionControl_RevNumber" at 1035.5,-656.17 h60
  text "SVN REV:" at 1541.5,-656.17 h60
  text ".PCB_Rev" at 2088,-656.17 h60
  text "REV:" at 2379.5,-656.17 h60
  text ".PRJ_Number" at 3224,-656.17 h60
  text "BOARD #:" at 3769.5,-656.17 h60
  text "PCB VIEWED FROM BOTTOM SIDE" at 6246,-656.17 h60
  text ".TID" at 3224,-859.5 h60
  text "TID #:" at 3769.5,-859.5 h60
  text "TEXAS INSTRUMENTS" at 904.5,-1064.84 h60
  text ".Print_Time" at 2169,-1064.84 h60
  text ".Print_Date" at 2898,-1064.84 h60
  text "GENERATED    :" at 3767.5,-1064.84 h60
  text ".plot_File_Name" at 5440.5,-1064.84 h60
  text "PLOT NAME =" at 6246,-1064.84 h60
M9 Title Sheet:
  drawing of 57 lines, arcs and shapes, not listed
  text "1" at 739.84,8036.5 h70
  text "2" at 3235.5,8036.5 h70
  text "3" at 5724.84,8036.5 h70
  text "4" at 8231.51,8036.5 h70
  text "5" at 10730.5,8036.5 h70
  text "6" at 13235.5,8036.5 h70
  text "A" at -416.5,6893.5 h70
  text "A" at 14383.5,6893.5 h70
  text "B" at -416.5,4513.5 h70
  text "B" at 14383.5,4513.5 h70
  text "C" at -416.5,2138.5 h70
  text "C" at 14383.5,2138.5 h70
  text "PROJECT TITLE:" at 11343.5,277.5 h45
  text "TIDA-01322" at 11393.5,144.17 h70
  text "DESIGNED FOR:" at 11343.5,-23.5 h45
  text ".PRJ_Customer" at 11393.5,-163.5 h70
  text "D" at -416.5,-231.5 h70
  text "D" at 14383.5,-231.5 h70
  text "FILE NAME:" at 11343.5,-323.5 h45
  text ".PCB_File_Name_No_Path" at 11393.5,-443.5 h70
  text "Texas Instruments (TI) and/or its licensors do not warrant the accuracy or completeness of this specification" at 6374,-605.34 h45
  text "ENGINEER:" at 11343.5,-613.5 h45
  text "LAYOUT BY:" at 12848.5,-613.5 h45
  text "or any information contained therein. TI and/or its licensors do not warrant that this design will meet" at 6329.01,-718 h45
  text "Jari Niemelä" at 12899,-768.49 h70
  text "the specifications, will be suitable for your application or fit for any particular purpose, or will operate in" at 6329.01,-830.67 h45
  text ".Layer_Name" at 577,-858.49 h60
  text "ALTIUM DESIGNER VERSION:" at 12848.5,-923.5 h45
  text "an implementation. TI and/or its licensors do not warrant that the design is production worthy. You should" at 6329.01,-943.33 h45
  text "completely validate and test your design implementation to confirm the system functionality for your application." at 6374,-1056 h45
  text ".print_Scale" at 11393.5,-1056.83 h70
  text ".Application_BuildNumber" at 12899,-1056.83 h70
  text "1" at 739.84,-1263.5 h70
  text "2" at 3235.5,-1263.5 h70
  text "3" at 5724.84,-1263.5 h70
  text "4" at 8231.51,-1263.5 h70
  text "5" at 10730.5,-1263.5 h70
  text "6" at 13235.5,-1263.5 h70
M10 Fab Notes:
  drawing of 173 lines, arcs and shapes, not listed
  text "DESIGN INFORMATION" at 12378.02,6201 h60
  text "MIN. TRACK WIDTH:" at 11733.46,6021 h60
  text "MIL" at 12984.46,6021 h60
  text "8" at 12821.7,6013 h60
  text "MIN. CLEARANCE:" at 11733.46,5889 h60
  text "0.2" at 12769.7,5889 h60
  text "mm" at 12984.46,5889 h60
  text "MIN. VIA PAD SIZE:" at 11733.46,5757 h60
  text "24" at 12799.71,5757 h60
  text "MIL" at 12984.46,5757 h60
  text "0.05mm (2MIL)" at 12428.46,5615.29 h60
  text "MINIMUM ANNULAR RING" at 11404.23,5611 h60
  text "EXTERNAL" at 13136.46,5611 h60
  text "PER" at 11604.23,5493 h60
  text "IPC-D-275 CLASS 2 LEVEL C" at 11824.23,5493 h60
  text "MIL, HOLES" at 13312.46,5380.71 h60
  text "+/-" at 12920,5380 h60
  text "+/-" at 13774,5380 h60
  text "REGISTRATION TOLERANCES:" at 11404.23,5375 h60
  text "METAL" at 12604,5375 h60
  text "5" at 13180.2,5375 h60
  text "3" at 14013.2,5375 h60
  text "MIL" at 14129.46,5375 h60
  text "+/-" at 13774,5262 h60
  text "HOLE SIZE TOLERANCE (UNLESS OTHERWISE SPECIFIED):" at 11404.23,5257 h60
  text "3" at 14013.2,5257 h60
  text "MIL" at 14129.46,5257 h60
  text "MATERIAL:" at 11329.46,5047.54 h60
  text "FR-4 High Tg" at 12315.9,4907.21 h60
  text "FR-408" at 11750.46,4898.64 h60
  text "OTHER" at 13238.46,4898.64 h60
  text "X" at 12161,4895 h60
  text "62 MIL (1.6mm) +/-10%" at 12070.56,4735.92 h60
  text "THICKNESS:" at 11404.23,4731.64 h60
  text "X" at 11942.4,4731.64 h60
  text "OTHER" at 13355.46,4731.64 h60
  text "TOLERANCE:" at 11404.23,4573.64 h60
  text "X" at 12243.53,4573.64 h60
  text "ANSI IPC-6012 TYPE 3 CLASS 2" at 12430.48,4573.64 h60
  text "OTHER +/-" at 12430.46,4417.64 h60
  text "BOW & TWIST:" at 11404.23,4260.64 h60
  text "X" at 12243.53,4260.64 h60
  text "ANSI IPC-6012 TYPE 3 CLASS 2" at 12430.48,4260.64 h60
  text "OTHER +/-" at 12430.46,4102.13 h60
  text "DRILLING:" at 11329.46,3963.64 h60
  text "REFERENCE:" at 11404.23,3846.64 h60
  text "X" at 12052.46,3846.64 h60
  text "AS SHOWN" at 12239.46,3846.64 h60
  text "X" at 12953.46,3846.64 h60
  text "NC_DRILL FILES" at 13090.46,3846.64 h60
  text "PTH COPPER THICKNESS:" at 11404.23,3688.64 h60
  text "X" at 12534.46,3688.64 h60
  text "20-30 um" at 12671.46,3688.64 h60
  text "OTHER" at 13388.46,3688.64 h60
  text "BOARD FINISH:" at 11329.46,3529.64 h60
  text "SILKSCREEN:" at 11484.68,3411.64 h60
  text "X" at 12433.46,3411.64 h60
  text "TOP" at 12559.46,3411.64 h60
  text "X" at 12943.46,3411.64 h60
  text "BOTTOM" at 13070.46,3411.64 h60
  text "SILKSCREEN COLOR:" at 11484.68,3244.64 h60
  text "X" at 12432.42,3244.64 h60
  text "WHITE" at 12559.46,3244.64 h60
  text "OTHER" at 13070.46,3244.64 h60
  text "X" at 12563.42,3085.44 h60
  text "GREEN" at 12690.46,3085.44 h60
  text "OTHER" at 13308.46,3085.44 h60
  text "SOLDER RESIST COLOR:" at 11484.68,3074.64 h60
  text "X" at 12563.42,2915.44 h60
  text "MATTE" at 12690.46,2915.44 h60
  text "SEMI-GLOSS" at 13308,2914.8 h60
  text "IMMERSION GOLD (ENIG)" at 12390.46,2726.92 h60
  text "ENEPIG" at 13728,2723.64 h60
  text "SURFACE FINISH:" at 11329.46,2722.64 h60
  text "X" at 12203.51,2722.64 h60
  text "IMM. TIN/SILVER OR EQUIV" at 11659,2565.64 h60
  text "OTHER" at 13090.46,2565.64 h60
  text "ARRAY/PANEL:" at 11329.46,2386.64 h60
  text "CUT AND TRIM PER M1 BOARD OUTLINE" at 12390.46,2382.35 h60
  text "N.C. ROUTE" at 12390.46,2230.64 h60
  text "X" at 13069.46,2230.64 h60
  text "V. SCORE" at 13256.46,2230.64 h60
  text "CERTIFICATION:" at 11329.46,2093.64 h60
  text "MATERIALS AND WORKMANSHIP FOR ALL PCBS" at 12054.46,2093.64 h60
  text "TO MEET OR EXCEED THE REQUIREMENTS OF:" at 12054.46,1995.64 h60
  text "X" at 11680.96,1859.13 h60
  text "ANSI IPC-A-600F CLASS ->" at 11819.96,1859.13 h60
  text "X" at 13459.02,1859.13 h60
  text "2" at 13577.96,1859.14 h60
  text "1" at 13262.96,1857.64 h60
  text "3" at 13931.96,1857.64 h60
  text "X" at 12495.02,1699.64 h60
  text "RoHS" at 12631.96,1699.64 h60
  text "OTHER" at 13276.36,1699.64 h60
  text "PER ORDER" at 13673.42,1699.64 h60
  text "ALL BOARDS MUST MEET OR EXCEED UL94-V0 REQUIREMENTS." at 11357,1534 h60
  text "PCB MUST BEAR THE UL94V-0 UL REGISTERED MATERIAL ID NUMBER" at 11357,1414 h60
  text "ADDITIONAL REQUIREMENTS:" at 11329.46,1240.64 h60
  text "MICROSECTION:" at 11404.23,1125.64 h60
  text "YES" at 12309.96,1125.64 h60
  text "REQUIRED" at 13171.46,969.49 h60
  text "BARE BOARD ELEC. TEST:" at 11404.23,966.64 h60
  text "NONE" at 12709.96,966.64 h60
  text "X" at 13044.46,966.64 h60
  text "PER ORDER" at 13763.46,966.64 h60
  text ".Layer_Name" at 577,-858.49 h60
M11 Gerber Information:
  lines w10: -292,-930.17 6308,-930.17 ; -292,-726.83 6310,-726.83 ; -292,-523.5 -292,-1133.5 3713,-1133.5 6310,-1133.5 6310,-523.5 -291.5,-523.5 -291.5,-1133.5 1284,-1133.5 ; 2173,-1133.5 2173,-523.5 ; 3440,-726.83 3440,-523.5 ; 4280,-726.83 4280,-523.5 ; 4902,-1140 4902,-937.17
  text "ALL ARTWORK VIEWED FROM TOP SIDE" at -228.5,-655.67 h60
  text "BOARD #:" at 2248,-655.67 h60
  text ".PRJ_Number" at 2793.5,-655.67 h60
  text "REV:" at 3638,-655.67 h60
  text ".PCB_Rev" at 3929.5,-655.67 h60
  text "SVN REV:" at 4476,-655.67 h60
  text ".VersionControl_RevNumber" at 4982,-655.67 h60
  text "LAYER NAME =" at -228.5,-858.49 h60
  text "TID #:" at 2248,-859 h60
  text ".TID" at 2793.5,-859 h60
  text "PLOT NAME =" at -228.5,-1064.34 h60
  text ".plot_File_Name" at 577,-1064.34 h60
  text "GENERATED    :" at 2250,-1064.34 h60
  text ".Print_Date" at 3119.5,-1064.34 h60
  text ".Print_Time" at 3848.5,-1064.34 h60
  text "TEXAS INSTRUMENTS" at 5113,-1064.34 h60
M12 Stackup:
  drawing of 191 lines, arcs and shapes, not listed
  text "Layer" at 9790.34,7830 h60
  text "Name" at 10200.26,7830 h60
  text "Material" at 11130,7830 h60
  text "Thickness" at 11989.77,7830 h60
  text "Constant" at 12639.6,7830 h60
  text "Board Layer Stack" at 13209.46,7830 h60
  text "1" at 9790.34,7710 h60
  text "Top Overlay" at 10200.26,7710 h60
  text "2" at 9790.34,7590 h60
  text "Top Solder" at 10200.26,7590 h60
  text "Solder Resist" at 11130,7590 h60
  text "0.40mil" at 11989.77,7590 h60
  text "3.5" at 12639.6,7590 h60
  text "3" at 9790.34,7470 h60
  text "Top Layer" at 10200.26,7470 h60
  text "Copper" at 11130,7470 h60
  text "1.40mil" at 11989.77,7470 h60
  text "4" at 9790.34,7350 h60
  text "Dielectric1" at 10200.26,7350 h60
  text "FR-4" at 11130,7350 h60
  text "59.20mil" at 11989.77,7350 h60
  text "4.8" at 12639.6,7350 h60
  text "5" at 9790.34,7230 h60
  text "Bottom Layer" at 10200.26,7230 h60
  text "Copper" at 11130,7230 h60
  text "1.40mil" at 11989.77,7230 h60
  text "6" at 9790.34,7110 h60
  text "Bottom Solder" at 10200.26,7110 h60
  text "Solder Resist" at 11130,7110 h60
  text "0.40mil" at 11989.77,7110 h60
  text "3.5" at 12639.6,7110 h60
  text "7" at 9790.34,6990 h60
  text "Bottom Overlay" at 10200.26,6990 h60
  text ".Layer_Name" at 577,-858.49 h60
M13 Component Bodies Top:
  text ".Layer_Name" at 577,-858.49 h60
M14 Component Bodies Bottom:
  text ".Layer_Name" at 577,-858.49 h60
M15 Courtyards Top:
  text ".Layer_Name" at 577,-858.49 h60
M16 Courtyards Bottom:
  text ".Layer_Name" at 577,-858.49 h60
Drill Drawing:
  lines w10: 5336.16,2754.18 5349.99,2754.18 5363.82,2740.35 5377.66,2754.18 5391.49,2754.18 5377.66,2768.02 5391.49,2781.85 5377.66,2781.85 5363.82,2795.68 5349.99,2781.85 5336.16,2781.85 5349.99,2768.02 5336.16,2754.18 ; 5336.16,2864.85 5391.49,2864.85 5391.49,2920.18 5336.16,2920.18 5336.16,2864.85 ; 5336.16,2989.35 5363.82,3003.18 5391.49,2989.35 5377.66,3017.02 5391.49,3044.68 5363.82,3030.85 5336.16,3044.68 5349.99,3017.02 5336.16,2989.35 ; 5336.16,3127.68 5349.99,3127.68 5363.82,3113.85 5377.66,3127.68 5391.49,3127.68 5377.66,3141.52 5391.49,3155.35 5377.66,3155.35 5363.82,3169.18 5349.99,3155.35 5336.16,3155.35 5349.99,3141.52 5336.16,3127.68 ; 5336.16,3293.68 5391.49,3293.68 5363.82,3238.35 5336.16,3293.68 ; 5347.23,3133.22 5355.52,3133.22 5363.82,3124.92 5372.12,3133.22 5380.43,3133.22 5372.12,3141.52 5380.43,3149.82 5372.12,3149.82 5363.82,3158.12 5355.52,3149.82 5347.23,3149.82 5355.52,3141.52 5347.23,3133.22
  lines w12: 5286,2703 8518.19,2703 ; 5286,3325.5 8518.19,3325.5 ; 5624.01,2578.5 5624.01,3450 ; 5956.17,2578.5 5956.17,3450 ; 6592.65,2578.5 6592.65,3450 ; 6851.85,2578.5 6851.85,3450 ; 7227.09,2578.5 7227.09,3450 ; 7951.64,2578.5 7951.64,3450 ; 5286,2578.5 8518.19,2578.5 8518.19,3450 5286,3450 5286,2578.5
  text "Symbol" at 5360.7,3362.85 h72
  text "Quantity" at 5661.36,3362.85 h72
  text "Finished Hole Size" at 5993.52,3362.85 h72
  text "Plated" at 6630,3362.85 h72
  text "Hole Type" at 6889.2,3362.85 h72
  text "Drill Layer Pair" at 7264.44,3362.85 h72
  text "Hole Tolerance" at 7988.99,3362.85 h72
  text "9" at 5661.36,3238.35 h60
  text "7.87mil (0.200mm)" at 5993.52,3238.35 h60
  text "PTH" at 6630,3238.35 h60
  text "Round" at 6889.2,3238.35 h60
  text "Top Layer - Bottom Layer" at 7264.44,3238.35 h60
  text "29" at 5661.36,3113.85 h60
  text "10.00mil (0.254mm)" at 5993.52,3113.85 h60
  text "PTH" at 6630,3113.85 h60
  text "Round" at 6889.2,3113.85 h60
  text "Top Layer - Bottom Layer" at 7264.44,3113.85 h60
  text "8" at 5661.36,2989.35 h60
  text "16.00mil (0.406mm)" at 5993.52,2989.35 h60
  text "PTH" at 6630,2989.35 h60
  text "Round" at 6889.2,2989.35 h60
  text "Top Layer - Bottom Layer" at 7264.44,2989.35 h60
  text "9" at 5661.36,2864.85 h60
  text "40.00mil (1.016mm)" at 5993.52,2864.85 h60
  text "PTH" at 6630,2864.85 h60
  text "Round" at 6889.2,2864.85 h60
  text "Top Layer - Bottom Layer" at 7264.44,2864.85 h60
  text "15" at 5661.36,2740.35 h60
  text "98.43mil (2.500mm)" at 5993.52,2740.35 h60
  text "PTH" at 6630,2740.35 h60
  text "Round" at 6889.2,2740.35 h60
  text "Top Layer - Bottom Layer" at 7264.44,2740.35 h60
  text "70 Total" at 5661.36,2615.85 h60
  text ".Layer_Name" at 577,-858.49 h60
M17 Embedded Cavity:
  text ".Layer_Name" at 577,-858.49 h60
M18 Embedded Assembly:
  text ".Layer_Name" at 577,-858.49 h60
M19 Embedded Keepout:
  text ".Layer_Name" at 577,-858.49 h60

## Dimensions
0,0 to 3530,0 on M2 Board Dimensions
0,0 to 0,2780 on M2 Board Dimensions
0,-400 to 1000,-400 on M2 Board Dimensions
